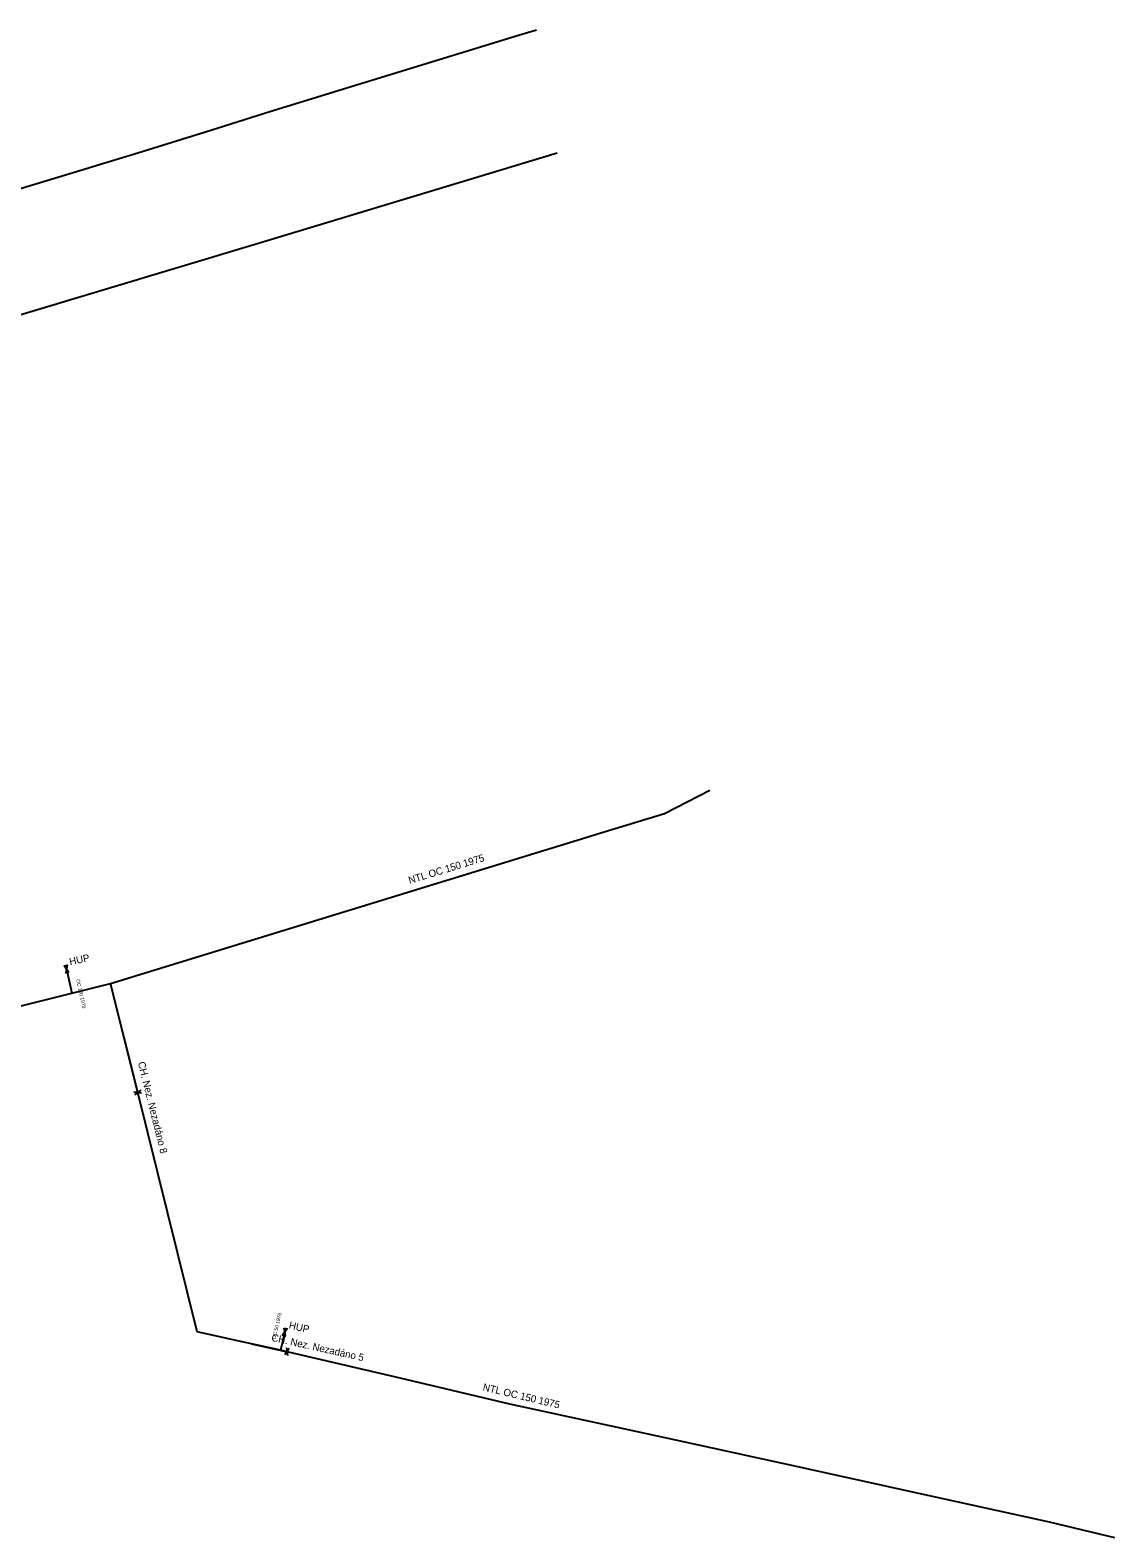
# Model space of a CAD drawing. Extents: x -743325 to -742825, y -1051501 to -1050981.
# Drawn here: x -742975 to -742825.5, y -1051322.1 to -1051114.4 of the extents above; entities that cross this region are included whole.
import ezdxf

# ---------------------------------------------------------------- set-up
doc = ezdxf.new("R2010")
doc.units = 0
for name, color, linetype in [('NT OP Chráni_ka - provoz', 7, 'Continuous'), ('NT Úsek p_ípojky - provoz', 7, 'Continuous'), ('NT Úsek plynovodu - provoz', 7, 'Continuous'), ('NT_HUP_24_popis', 7, 'Continuous'), ('ST Úsek plynovodu - provoz', 7, 'Continuous'), ('Vrstva 1', 7, 'Continuous')]:
    doc.layers.add(name, color=color, linetype=linetype)

msp = doc.modelspace()

# ---------------------------------------------------------------- linework, layer by layer
at = {"layer": 'NT OP Chráni_ka - provoz'}
for points in [[(-742960.19, -1051260.76), (-742962.12, -1051253)], [(-742944.49, -1051295.38), (-742939.61, -1051296.47)]]:
    msp.add_lwpolyline(points, dxfattribs=at)
at = {"layer": 'NT Úsek p_ípojky - provoz'}
for points in [[(-742970.01, -1051243.73), (-742969.29, -1051247.06)], [(-742939.92, -1051293.76), (-742940.49, -1051296.27)]]:
    msp.add_lwpolyline(points, dxfattribs=at)
at = {"layer": 'NT Úsek plynovodu - provoz'}
for points in [[(-742905.2, -1051114.38), (-742907.71, -1051115.12), (-742933.01, -1051122.87), (-742942.73, -1051125.88), (-742950.11, -1051128.19), (-742960.77, -1051131.52), (-742966.82, -1051133.35), (-742966.83, -1051133.35), (-742968.17, -1051133.76), (-742987.77, -1051139.71), (-743002.3, -1051144.12), (-743015.04, -1051147.98), (-743019.86, -1051149.44), (-743021.06, -1051149.81), (-743070.97, -1051164.82)], [(-742963.93, -1051245.72), (-742897.81, -1051225.43), (-742896.94, -1051225.14), (-742887.56, -1051222.29), (-742881.35, -1051219.09)], [(-743057.41, -1051269.53), (-743047.57, -1051271.23), (-743044.8, -1051270.35), (-742983.69, -1051250.65), (-742969.29, -1051247.06), (-742963.93, -1051245.72)], [(-742825.5, -1051322.1), (-742834.49, -1051319.96), (-742852.54, -1051315.99), (-742870.02, -1051312.14), (-742887.49, -1051308.31), (-742908.89, -1051303.71), (-742924.03, -1051300.1), (-742939.61, -1051296.47), (-742940.49, -1051296.27), (-742944.49, -1051295.38), (-742946.44, -1051294.94), (-742951.98, -1051293.71), (-742960.19, -1051260.76), (-742963.93, -1051245.72)]]:
    msp.add_lwpolyline(points, dxfattribs=at)
at = {"layer": 'ST Úsek plynovodu - provoz'}
msp.add_lwpolyline([(-742902.36, -1051131.35), (-742943.88, -1051143.86), (-742998.83, -1051160.34), (-743019.29, -1051166.45), (-743044.23, -1051173.62), (-743063.43, -1051177.51), (-743072.45, -1051184.99)], dxfattribs=at)
at = {"layer": 'Vrstva 1'}
for p, q in [((-742959.65, -1051260.83), (-742960.72, -1051260.68)), ((-742959.75, -1051260.44), (-742960.62, -1051261.07)), ((-742939.3, -1051296.02), (-742939.92, -1051296.91)), ((-742939.69, -1051295.93), (-742939.53, -1051297))]:
    msp.add_line(p, q, dxfattribs=at)
for points in [[(-742970.31, -1051243.29), (-742969.92, -1051243.2), (-742970.1, -1051244.26), (-742969.71, -1051244.18), (-742970.31, -1051243.29)], [(-742940, -1051293.23), (-742939.61, -1051293.31), (-742940.22, -1051294.2), (-742939.83, -1051294.29), (-742940, -1051293.23)]]:
    msp.add_lwpolyline(points, dxfattribs=at)

# ---------------------------------------------------------------- texts
at = {"layer": 'NT OP Chráni_ka - provoz'}
for s, rotation, p in [('CH. Nez. Nezadáno 8', 283.9754, (-742960.18, -1051256.63)), ('CH. Nez. Nezadáno 5', 347.4314, (-742941.83, -1051294.95))]:
    msp.add_text(s, height=1, rotation=rotation, dxfattribs=at).set_placement(p)
at = {"layer": 'NT Úsek p_ípojky - provoz'}
for s, rotation, p in [('OC 100 1976', 282.1925, (-742968.67, -1051245.18)), ('OC 50 1976', 77.2155, (-742941.18, -1051294.79))]:
    msp.add_text(s, height=0.5, rotation=rotation, dxfattribs=at).set_placement(p)
at = {"layer": 'NT Úsek plynovodu - provoz'}
for rotation, p in [(17.0601, (-742922.7, -1051232.02)), (346.5611, (-742912.69, -1051301.78))]:
    msp.add_text('NTL OC 150 1975', height=1, rotation=rotation, dxfattribs=at).set_placement(p)
at = {"layer": 'NT_HUP_24_popis'}
for rotation, p in [(12.19, (-742969.51, -1051243.23)), (347.22, (-742939.42, -1051293.26))]:
    msp.add_text('HUP', height=1, rotation=rotation, dxfattribs=at).set_placement(p)

doc.saveas('drawing.dxf')
